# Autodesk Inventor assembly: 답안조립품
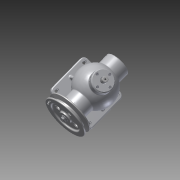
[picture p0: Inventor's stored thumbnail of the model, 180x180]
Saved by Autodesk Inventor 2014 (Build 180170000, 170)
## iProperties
Created: 2017-01
Part Number: 답안조립품
Document SubType Name: Assembly
Designer: ksu
Author: ksu
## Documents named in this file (19)
- C:\Users\ksu\Desktop\470118V1009\470118V1009\답안조립품.iam
- C:\Users\ksu\Desktop\470118V1009\470118V1009\1 본체.ipt
- C:\Users\ksu\Desktop\470118V1009\470118V1009\V-벨트풀리.ipt
- C:\Users\ksu\Desktop\470118V1009\470118V1009\너트 M8.ipt
- C:\Users\ksu\Desktop\470118V1009\470118V1009\뒤커버.ipt
- C:\Users\ksu\Desktop\470118V1009\470118V1009\멈춤링- 15 x 1.ipt
- C:\Users\ksu\Desktop\470118V1009\470118V1009\멈춤링- 35x1.6.ipt
- KS B 1336 - 35x1.6.ipt
- C:\Users\ksu\Desktop\470118V1009\470118V1009\베어링- 6202.ipt
- KS B 2023 - 6202 - 15 x 35 x 11 - 7.8.ipt
- C:\Users\ksu\Desktop\470118V1009\470118V1009\볼트 M4 x 12.ipt
- C:\Users\ksu\Desktop\470118V1009\470118V1009\볼트 M4 x 16.ipt
- C:\Users\ksu\Desktop\470118V1009\470118V1009\부시.ipt
- C:\Users\ksu\Desktop\470118V1009\470118V1009\상부커버.ipt
- C:\Users\ksu\Desktop\470118V1009\470118V1009\슬라이드.ipt
- C:\Users\ksu\Desktop\470118V1009\470118V1009\앞커버.ipt
- C:\Users\ksu\Desktop\470118V1009\470118V1009\오일실 15 30 7.ipt
- C:\Users\ksu\Desktop\470118V1009\470118V1009\키 4 x 4 x 12.ipt
- C:\Users\ksu\Desktop\470118V1009\470118V1009\편심축.ipt
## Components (17 placed, 6 different names)
1. V-벨트풀리:1 — Mate:4, Mate:5, Mate:6
2. KS B 1336 - 35x1.6:1 — Mate:26, Mate:31
3. KS B 2023 - 6202 - 15 x 35 x 11 - 7.8:1 — Mate:13, Mate:16, Mate:17
4. KS B 1021 - 에 따름 ISO 1207 - 미터 A  M 4 x 12:1 — Mate:38, Mate:43
5. ISO 4762 M4 x 16:1 — Mate:45, Mate:51
6. KS B 2023 - 6202 - 15 x 35 x 11 - 7.8:2 — Mate:22, Mate:24
7. 1 본체:1 — Mate:26, Mate:27, Mate:28, Mate:29, Mate:30, Mate:31, Mate:34, Mate:35, Mate:36, Mate:37, Mate:40
8. KS B 1021 - 에 따름 ISO 1207 - 미터 A  M 4 x 12:2 — Mate:40, Mate:61
9. KS B 1021 - 에 따름 ISO 1207 - 미터 A  M 4 x 12:3 — Mate:39, Mate:44
10. KS B 1021 - 에 따름 ISO 1207 - 미터 A  M 4 x 12:4 — Mate:41, Mate:42
11. ISO 4762 M4 x 16:2 — Mate:48, Mate:50
12. ISO 4762 M4 x 16:3 — Mate:47, Mate:52
13. ISO 4762 M4 x 16:4 — Mate:46, Mate:49
14. ISO 4762 M4 x 16:5 — Mate:53, Mate:57
15. ISO 4762 M4 x 16:6 — Mate:54, Mate:58
16. ISO 4762 M4 x 16:7 — Mate:55, Mate:60
17. ISO 4762 M4 x 16:8 — Mate:56, Mate:59
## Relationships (42: Mate 42)
- Mate:4: V-벨트풀리:1
- Mate:5: V-벨트풀리:1
- Mate:6: V-벨트풀리:1
- Mate:13: KS B 2023 - 6202 - 15 x 35 x 11 - 7.8:1
- Mate:16: KS B 2023 - 6202 - 15 x 35 x 11 - 7.8:1
- Mate:17: KS B 2023 - 6202 - 15 x 35 x 11 - 7.8:1
- Mate:22: KS B 2023 - 6202 - 15 x 35 x 11 - 7.8:2
- Mate:24: KS B 2023 - 6202 - 15 x 35 x 11 - 7.8:2
- Mate:26: KS B 1336 - 35x1.6:1 ↔ 1 본체:1
- Mate:27: 1 본체:1
- Mate:28: 1 본체:1
- Mate:29: 1 본체:1
- Mate:30: 1 본체:1
- Mate:31: KS B 1336 - 35x1.6:1 ↔ 1 본체:1
- Mate:34: 1 본체:1
- Mate:35: 1 본체:1
- Mate:36: 1 본체:1
- Mate:37: 1 본체:1
- Mate:38: KS B 1021 - 에 따름 ISO 1207 - 미터 A  M 4 x 12:1
- Mate:39: KS B 1021 - 에 따름 ISO 1207 - 미터 A  M 4 x 12:3
- Mate:40: 1 본체:1 ↔ KS B 1021 - 에 따름 ISO 1207 - 미터 A  M 4 x 12:2
- Mate:41: KS B 1021 - 에 따름 ISO 1207 - 미터 A  M 4 x 12:4
- Mate:42: KS B 1021 - 에 따름 ISO 1207 - 미터 A  M 4 x 12:4
- Mate:43: KS B 1021 - 에 따름 ISO 1207 - 미터 A  M 4 x 12:1
- Mate:44: KS B 1021 - 에 따름 ISO 1207 - 미터 A  M 4 x 12:3
- Mate:45: ISO 4762 M4 x 16:1
- Mate:46: ISO 4762 M4 x 16:4
- Mate:47: ISO 4762 M4 x 16:3
- Mate:48: ISO 4762 M4 x 16:2
- Mate:49: ISO 4762 M4 x 16:4
- Mate:50: ISO 4762 M4 x 16:2
- Mate:51: ISO 4762 M4 x 16:1
- Mate:52: ISO 4762 M4 x 16:3
- Mate:53: ISO 4762 M4 x 16:5
- Mate:54: ISO 4762 M4 x 16:6
- Mate:55: ISO 4762 M4 x 16:7
- Mate:56: ISO 4762 M4 x 16:8
- Mate:57: ISO 4762 M4 x 16:5
- Mate:58: ISO 4762 M4 x 16:6
- Mate:59: ISO 4762 M4 x 16:8
- Mate:60: ISO 4762 M4 x 16:7
- Mate:61: KS B 1021 - 에 따름 ISO 1207 - 미터 A  M 4 x 12:2
